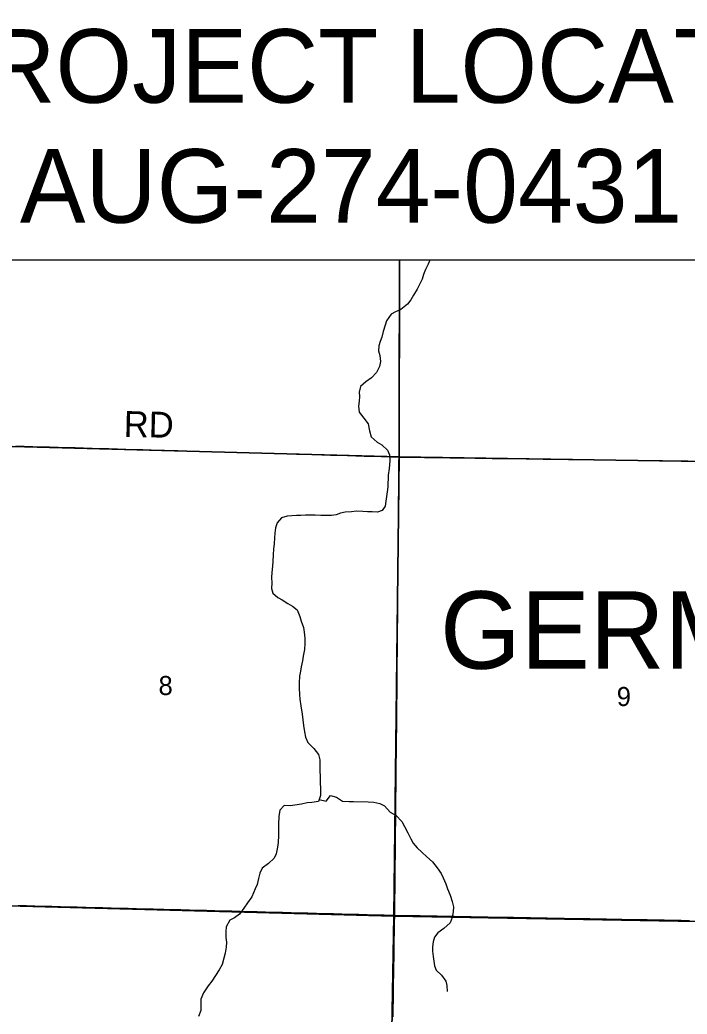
# Model space of a CAD drawing. Extents: x 0 to 34, y 0 to 22.
# Drawn here: x 2.963 to 4.43, y 17.239 to 19.428 of the extents above; entities that cross this region are included whole.
import ezdxf

# ---------------------------------------------------------------- set-up
doc = ezdxf.new("R2010")
doc.units = 0
for name, color, linetype in [('GM_X_Corporation', 7, 'Continuous'), ('GM_X_County_Road', 7, 'Continuous'), ('GM_X_County_Road_Text', 7, 'Continuous'), ('GM_X_Minor_River', 7, 'Continuous'), ('GM_X_Section_Text', 7, 'Continuous'), ('GM_X_State_Route', 7, 'Continuous'), ('GM_X_Township_Road', 7, 'Continuous'), ('GM_X_Township_Text', 7, 'Continuous'), ('SH_Text', 7, 'Continuous')]:
    doc.layers.add(name, color=color, linetype=linetype)

msp = doc.modelspace()

# ---------------------------------------------------------------- linework, layer by layer
at = {"layer": 'GM_X_Corporation'}
for points in [[(4.7562, 19.4462), (4.7881, 19.4457), (4.8082, 19.4446), (4.7982, 18.4503), (3.7969, 18.4658), (3.7979, 18.8986)], [(3.7979, 18.8986), (3.7969, 18.4658), (2.7802, 18.4929), (2.7874, 18.8986)]]:
    msp.add_lwpolyline(points, dxfattribs=at)
for points in [[(3.7969, 18.4658), (3.785, 17.4549), (2.771, 17.4824), (2.7802, 18.4929)], [(3.7969, 18.4658), (4.7982, 18.4503), (4.7862, 17.4375), (3.785, 17.4549)], [(3.785, 17.4549), (3.7672, 16.4521), (2.7618, 16.4707), (2.771, 17.4824)], [(4.7862, 17.4375), (4.7695, 16.4317), (3.7672, 16.4521), (3.785, 17.4549)]]:
    msp.add_lwpolyline(points, close=True, dxfattribs=at)
at = {"layer": 'GM_X_County_Road'}
msp.add_lwpolyline([(2.9535, 18.49), (2.9721, 18.4895), (2.9908, 18.4889), (3.0094, 18.4884), (3.028, 18.4879), (3.0467, 18.4873), (3.0653, 18.4868), (3.0839, 18.4862), (3.1026, 18.4857), (3.1212, 18.4852), (3.1398, 18.4846), (3.1585, 18.4841), (3.1771, 18.4836), (3.1957, 18.483), (3.2144, 18.4825), (3.233, 18.4819), (3.2516, 18.4814), (3.2703, 18.4809), (3.2809, 18.4806), (3.2915, 18.4803), (3.3102, 18.4797), (3.3288, 18.4792), (3.3474, 18.4786), (3.3661, 18.4781), (3.3847, 18.4776), (3.4033, 18.477), (3.422, 18.4765), (3.4406, 18.4759), (3.4592, 18.4754), (3.4779, 18.4748), (3.4965, 18.4743), (3.5152, 18.4738), (3.5338, 18.4732), (3.5524, 18.4727), (3.5711, 18.4721), (3.5897, 18.4716), (3.6083, 18.4711), (3.627, 18.4705), (3.6456, 18.47), (3.6642, 18.4694), (3.6829, 18.4689), (3.7015, 18.4683), (3.7201, 18.4678), (3.7388, 18.4673), (3.7574, 18.4667), (3.776, 18.4662), (3.7863, 18.4659), (3.7965, 18.4656), (3.8151, 18.4653), (3.8338, 18.4651), (3.8524, 18.4648), (3.8711, 18.4645), (3.8897, 18.4643), (3.9084, 18.464), (3.927, 18.4638), (3.9456, 18.4635), (3.9643, 18.4633), (3.9829, 18.463), (4.0016, 18.4627), (4.0202, 18.4625), (4.0388, 18.4622), (4.0575, 18.462), (4.0761, 18.4617), (4.0948, 18.4615), (4.1134, 18.4612), (4.132, 18.4609), (4.1507, 18.4607), (4.1693, 18.4604), (4.188, 18.4602), (4.2066, 18.4599), (4.2252, 18.4596), (4.2439, 18.4594), (4.2625, 18.4591), (4.2812, 18.4589), (4.2912, 18.4587), (4.3012, 18.4586), (4.3199, 18.4584), (4.3385, 18.4581), (4.3572, 18.4579), (4.3758, 18.4577), (4.3944, 18.4575), (4.4131, 18.4573), (4.4317, 18.457)], dxfattribs=at)
at = {"layer": 'GM_X_Minor_River'}
msp.add_line((3.8644, 18.8986), (3.8609, 18.89), dxfattribs=at)
for points in [[(3.8609, 18.89), (3.8549, 18.8787), (3.8501, 18.867), (3.8472, 18.8568), (3.8413, 18.8452), (3.8365, 18.835), (3.8286, 18.8215), (3.8227, 18.8118), (3.8153, 18.8017), (3.8002, 18.7903), (3.7891, 18.7852), (3.7791, 18.7797), (3.7693, 18.7655), (3.7657, 18.7557), (3.7616, 18.7417), (3.7587, 18.7296), (3.755, 18.7198), (3.7518, 18.71), (3.7515, 18.6994), (3.7543, 18.6887), (3.7556, 18.6761), (3.7538, 18.6648), (3.7467, 18.6516), (3.7358, 18.6401), (3.7235, 18.6309), (3.7115, 18.6205), (3.7085, 18.6084), (3.7095, 18.5985), (3.7088, 18.5882), (3.7071, 18.5773), (3.7087, 18.5643), (3.719, 18.5511), (3.729, 18.5384), (3.7313, 18.5235), (3.7352, 18.5097), (3.7482, 18.4984), (3.7587, 18.4925), (3.7709, 18.4808), (3.7756, 18.4704), (3.7765, 18.4571), (3.7746, 18.44), (3.7727, 18.4256), (3.7722, 18.4001), (3.7704, 18.3888), (3.7677, 18.3683), (3.7663, 18.3573), (3.7593, 18.3476), (3.7489, 18.3444), (3.7372, 18.3447), (3.727, 18.3453), (3.7171, 18.3459), (3.7027, 18.3462), (3.6921, 18.3453), (3.6784, 18.3441), (3.6681, 18.3417), (3.6585, 18.3381), (3.6483, 18.3368), (3.6361, 18.3367), (3.6247, 18.3366), (3.6119, 18.3373), (3.602, 18.3375), (3.591, 18.3374), (3.5804, 18.3368), (3.5709, 18.3367), (3.5606, 18.3362), (3.5504, 18.3353), (3.5378, 18.3314), (3.5288, 18.3205), (3.5251, 18.3096), (3.5237, 18.2978), (3.5228, 18.2876), (3.5217, 18.2747), (3.5207, 18.2633), (3.52, 18.2504), (3.5193, 18.2363), (3.518, 18.2253), (3.5165, 18.2113), (3.5163, 18.2003), (3.5164, 18.1885), (3.5157, 18.1763), (3.5193, 18.166), (3.5297, 18.1566), (3.5395, 18.1515), (3.5518, 18.1432), (3.5623, 18.1376), (3.5727, 18.129), (3.5781, 18.1148), (3.5813, 18.1045), (3.5867, 18.0903), (3.588, 18.08), (3.5892, 18.067), (3.5893, 18.0549), (3.5883, 18.042), (3.586, 18.0272), (3.5843, 18.0173), (3.581, 18.0041), (3.5796, 17.9939), (3.5779, 17.9836), (3.5768, 17.9688), (3.5769, 17.957), (3.5777, 17.9429)], [(3.5777, 17.9429), (3.5786, 17.9323), (3.5802, 17.9178), (3.5832, 17.8995), (3.5852, 17.8869), (3.5865, 17.875), (3.5884, 17.8609), (3.5905, 17.8487), (3.5959, 17.8372), (3.6093, 17.8243), (3.6196, 17.8111), (3.622, 17.7989), (3.6221, 17.7852), (3.6222, 17.7757), (3.6227, 17.762), (3.6232, 17.7494), (3.624, 17.735), (3.6237, 17.7205), (3.6192, 17.7077), (3.6044, 17.7054), (3.5945, 17.7045), (3.5823, 17.7017), (3.5674, 17.6994), (3.5568, 17.6981), (3.5439, 17.6988), (3.5342, 17.688), (3.532, 17.6747), (3.5312, 17.6572), (3.5314, 17.6466), (3.5311, 17.6329), (3.5304, 17.6173), (3.529, 17.6071), (3.526, 17.5923), (3.522, 17.5825), (3.5093, 17.571), (3.4954, 17.5603), (3.4906, 17.5497), (3.4873, 17.538), (3.4843, 17.5248), (3.4803, 17.515), (3.4724, 17.4977), (3.463, 17.4846), (3.4551, 17.4726), (3.4453, 17.4591), (3.4345, 17.451), (3.4246, 17.4459), (3.4163, 17.4316), (3.4153, 17.4214), (3.4154, 17.4084), (3.4167, 17.3974), (3.4164, 17.3864), (3.4143, 17.3739), (3.411, 17.3629), (3.4076, 17.3485), (3.4009, 17.3365), (3.3931, 17.3245), (3.3845, 17.3122), (3.377, 17.3013), (3.3668, 17.2863), (3.3608, 17.272), (3.3603, 17.2473), (3.3551, 17.2341)], [(3.6207, 17.7121), (3.6363, 17.7084), (3.6461, 17.7204), (3.6589, 17.7167), (3.672, 17.7084), (3.6867, 17.7073), (3.6962, 17.7075), (3.7288, 17.7067), (3.7409, 17.706), (3.7545, 17.7031), (3.7643, 17.6979), (3.7769, 17.6839), (3.7904, 17.6764), (3.8026, 17.6632), (3.8084, 17.652), (3.8157, 17.6381), (3.8226, 17.6254), (3.8277, 17.6158), (3.8366, 17.6053), (3.8466, 17.5956), (3.8578, 17.5854), (3.8705, 17.5749), (3.8804, 17.5613), (3.8889, 17.549), (3.8936, 17.5393), (3.8997, 17.5259), (3.9033, 17.5155), (3.909, 17.5009), (3.9137, 17.4875), (3.9161, 17.4753), (3.9155, 17.4647), (3.9137, 17.4518), (3.9092, 17.4404), (3.8953, 17.4278), (3.8822, 17.4182), (3.8748, 17.4085), (3.8719, 17.3987), (3.8702, 17.3877), (3.8703, 17.3778), (3.8716, 17.366), (3.8729, 17.3557), (3.8749, 17.3458), (3.8785, 17.3358), (3.89, 17.3252), (3.8992, 17.3121), (3.902, 17.3025), (3.9025, 17.2892)]]:
    msp.add_lwpolyline(points, dxfattribs=at)
at = {"layer": 'GM_X_State_Route'}
msp.add_lwpolyline([(2.9585, 17.4787), (2.9771, 17.4782), (2.9957, 17.4777), (3.0144, 17.4772), (3.033, 17.4767), (3.0516, 17.4762), (3.0703, 17.4758), (3.0889, 17.4753), (3.1075, 17.4748), (3.1262, 17.4743), (3.1448, 17.4738), (3.1634, 17.4734), (3.1821, 17.4729), (3.2007, 17.4724), (3.2194, 17.4719), (3.238, 17.4714), (3.2566, 17.4709), (3.2681, 17.4706), (3.2795, 17.4704), (3.2981, 17.4699), (3.3168, 17.4694), (3.3354, 17.4689), (3.354, 17.4684), (3.3727, 17.4679), (3.3913, 17.4674), (3.4099, 17.467), (3.4286, 17.4665), (3.4472, 17.466), (3.4658, 17.4655), (3.4845, 17.465), (3.5031, 17.4645), (3.5218, 17.4641), (3.5404, 17.4636), (3.559, 17.4631), (3.5777, 17.4626), (3.5963, 17.4621), (3.6149, 17.4616), (3.6336, 17.4611), (3.6522, 17.4606), (3.6708, 17.4602), (3.6895, 17.4597), (3.7081, 17.4592), (3.7267, 17.4587), (3.7454, 17.4582), (3.764, 17.4577), (3.7756, 17.4574), (3.7871, 17.4571), (3.8058, 17.4568), (3.8244, 17.4564), (3.843, 17.4561), (3.8617, 17.4558), (3.8803, 17.4555), (3.899, 17.4551), (3.9176, 17.4548), (3.9362, 17.4545), (3.9549, 17.4541), (3.9735, 17.4538), (3.9922, 17.4535), (4.0108, 17.4531), (4.0294, 17.4528), (4.0481, 17.4525), (4.0667, 17.4521), (4.0854, 17.4518), (4.104, 17.4515), (4.1227, 17.4511), (4.1413, 17.4508), (4.1599, 17.4505), (4.1786, 17.4501), (4.1972, 17.4498), (4.2159, 17.4495), (4.2345, 17.4491), (4.2531, 17.4488), (4.2698, 17.4485), (4.2865, 17.4482), (4.3051, 17.4479), (4.3238, 17.4476), (4.3424, 17.4473), (4.3611, 17.447), (4.3797, 17.4467), (4.3984, 17.4463), (4.417, 17.446), (4.4356, 17.4457)], dxfattribs=at)
at = {"layer": 'GM_X_Township_Road'}
msp.add_lwpolyline([(3.7835, 17.2335), (3.7838, 17.2521), (3.7841, 17.2707), (3.7844, 17.2894), (3.7847, 17.308), (3.785, 17.3267), (3.7853, 17.3453), (3.7856, 17.364), (3.7859, 17.3826), (3.7862, 17.4012), (3.7865, 17.4199), (3.7868, 17.4385), (3.7871, 17.4571), (3.7873, 17.4757), (3.7875, 17.4944), (3.7877, 17.513), (3.7879, 17.5317), (3.7881, 17.5503), (3.7883, 17.569), (3.7885, 17.5876), (3.7887, 17.6062), (3.7889, 17.6249), (3.7891, 17.6435), (3.7893, 17.6622), (3.7895, 17.6808), (3.7897, 17.6994), (3.7898, 17.7181), (3.79, 17.7367), (3.7902, 17.7554), (3.7904, 17.774), (3.7906, 17.7926), (3.7908, 17.8113), (3.791, 17.8299), (3.7912, 17.8486), (3.7914, 17.8672), (3.7916, 17.8859), (3.7918, 17.9045), (3.792, 17.9231), (3.7922, 17.9415), (3.7924, 17.9598), (3.7925, 17.9785), (3.7927, 17.9971), (3.7928, 18.0158), (3.793, 18.0344), (3.7931, 18.053), (3.7933, 18.0717), (3.7934, 18.0903), (3.7936, 18.109), (3.7937, 18.1276), (3.7939, 18.1462), (3.794, 18.1649), (3.7942, 18.1835), (3.7944, 18.2022), (3.7945, 18.2208), (3.7947, 18.2394), (3.7948, 18.2581), (3.795, 18.2767), (3.7951, 18.2954), (3.7953, 18.314), (3.7954, 18.3327), (3.7956, 18.3513), (3.7957, 18.3699), (3.7959, 18.3886), (3.796, 18.4072), (3.7962, 18.4259), (3.7963, 18.4445), (3.7964, 18.455), (3.7965, 18.4656), (3.7966, 18.4842), (3.7968, 18.5401), (3.7969, 18.5774), (3.7979, 18.8986)], dxfattribs=at)
at = {"layer": 'SH_Text'}
msp.add_lwpolyline([(2.7075, 19.4692), (4.7562, 19.4692), (4.7562, 18.8986), (2.7075, 18.8986)], close=True, dxfattribs=at)

# ---------------------------------------------------------------- texts
at = {"layer": 'GM_X_County_Road_Text'}
msp.add_text('RD', height=0.05682, rotation=358.7853, dxfattribs=at).set_placement((3.1906, 18.5101))
at = {"layer": 'GM_X_Section_Text'}
for s, p in [('8', (3.2676, 17.9417)), ('9', (4.2755, 17.9175))]:
    msp.add_text(s, height=0.0419, rotation=0, dxfattribs=at).set_placement(p)
at = {"layer": 'GM_X_Township_Text'}
msp.add_text('GERMAN', height=0.17045, rotation=0, dxfattribs=at).set_placement((3.8869, 17.9996))
at = {"layer": 'SH_Text'}
for s, p in [('PROJECT LOCATION', (2.74, 19.2454)), ('AUG-274-0431', (2.9625, 18.9813))]:
    msp.add_text(s, height=0.162, dxfattribs=at).set_placement(p)

doc.saveas('drawing.dxf')
